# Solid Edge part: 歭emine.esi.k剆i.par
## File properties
Author: Türk
Template: Iso Part.par
Last saved by: Türk
Revision: 5
Application: Solid Edge
Accuracy: 0,990
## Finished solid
Body 1: solid body, 46 faces, 107 edges, 60 vertices.
  Faces by surface: cylinder 20, plane 12, torus 12, blend 2
  Edges by curve: circle 42, intersection 36, line 22, ellipse 7
Bounding box of the edges (mm; curved faces can reach further): 250.000 x 118.000 x 100.000, from (-225, 0, -25) to (25, 118, 75).
Cylindrical faces by radius (mm): R5 x2, R10.5 x4, R15 x10, R25 x4
Toroidal faces (ring radius, tube radius in mm): R11.5 r1 x4, R24 r1 x4, R380.6351 r5 x2, R400 r15 x2
Planar faces by outward normal: +x 1, +y 4, +z 1, -x 1, -y 4, -z 1
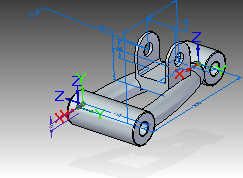
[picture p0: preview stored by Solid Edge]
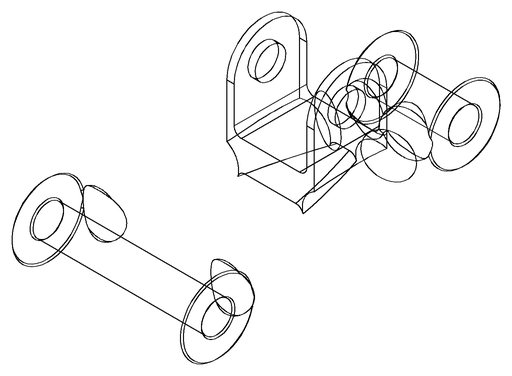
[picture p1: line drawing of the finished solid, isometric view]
